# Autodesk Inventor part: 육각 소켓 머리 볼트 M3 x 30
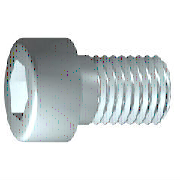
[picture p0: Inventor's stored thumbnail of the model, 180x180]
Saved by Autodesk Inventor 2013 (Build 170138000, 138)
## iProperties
IsCustomPart: 1
Created: 2012-02
Part Number: 육각 소켓 머리 볼트 M3 x 30
Material: 강철, 연강
Description: 6각 소켓 머리 캡 나사
Document SubType Name: Modeling
Standard: ISO 4762
Designer: mdu-01
Standard Revision: Fourth edition 2004-03-01
Standards Organization: ISO
Language: ko-KR
Size Designation: M3 x 30
Categories: <MemberInstance><Categories><Category DisplayName="조임쇠" InternalName="e4da775c-781d-43d5-af7c-5136215cf5a6" Mnemonic="FSTN"><Category DisplayName="볼트" InternalN
Density: 7.75 g/cm^3
Author: mdu-01
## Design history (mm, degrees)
sketch "스케치1"
  geometry: L1 (-0.867, 0)-(30, 0); L2 (30, 0)-(30, 1.5); L3 (30, 1.5)-(12, 1.5); L4 (12, 1.5)-(11.693, 1.5); L5 (11.693, 1.5)-(0, 1.5); L6 (0, 1.5)-(0, 2.75); L7 (0, 2.75)-(-3, 2.75); L8 (-3, 2.75)-(-3, 1.443); L9 (-3, 1.443)-(-1.7, 1.443); L10 (-1.7, 1.443)-(-0.867, 0); L11 (-9.6, 0)-(36.6, 0) reference; L12 (0, -0.55)-(0, 3.3) reference; L13 (12, 1.5)-(0, 1.5)
  constraints: 22 end point, 6 parallel, 2 collinear, 2 perpendicular, 1 horizontal, 1 point on line
  dimensions: "d1" = 18 distance from line of L3.end L2 (= GEL); "d2" = 0.30683 distance of L4.end L3.end (computed from GAL); "d3" = 3 distance between parallel lines of L8 L6 (= KOH); "d4" = 1.3 distance of L8.end L9.end (= INTI); "d5" = 60 deg angle of L10 L1; "d6" = 3 diameter of L3 L1 (= GD); "d7" = 3 diameter of L5 L1 (= BDM); "d8" = 2.88675 diameter of L9 L1 (= 1.1547 x SW); "d9" = 5.5 diameter of L7 L1 (= KOD); "d26" = 30 distance between parallel lines of L12 L2 (= NLG)
revolve "본체" sketch "스케치1" stored, may be unused: angle "d10" = 90 deg
sketch "스케치2"
  geometry: L1 (0, -3.85)-(0, 3.85) reference; L2 (-3.85, 0)-(3.85, 0) reference; L3 (1.443, 0)-(0.722, -1.25); L4 (0.722, -1.25)-(-0.722, -1.25); L5 (-0.722, -1.25)-(-1.443, 0); L6 (-1.443, 0)-(-0.722, 1.25); L7 (-0.722, 1.25)-(0.722, 1.25); L8 (0.722, 1.25)-(1.443, 0); 2 further points
  constraints: 12 end point, 1 coincident, 1 horizontal alignment, 1 point on line, 12 other
extrude "슬롯" join sketch "스케치2" stored distance "d11" = 10; taper "d12" = 0 deg
workplane "Work Plane1"
fillet "Fillet2" dims "d30" = 0.1 (= R)
body "Solid1"
fillet "모깎기1" dims "d17" = 0.3 (= RR)
feature "스레드" dims "d13" = 18 (= GEL), "d14" = 0
chamfer "모따기1" distance "d15" = 0.30673 (= -0.5 x SPD + 0.5 x GD); stored, may be unused: second distance "d16" = 0.30673 (= GUL), angle "d27" = 45 deg
other parameters: "GD" = 3 [user parameter; used in 2 equation terms], "NLG" = 30 [user parameter; used in 1 equation term], "GEL" = 18 [user parameter; used in 2 equation terms], "KOD" = 5.5 [user parameter; used in 1 equation term], "KOH" = 3 [user parameter; used in 1 equation term], "INTI" = 1.3 [user parameter; used in 1 equation term], "GAL" = 0.30673 (= 0.61345 x PTC) [user parameter; used in 1 equation term], "GUL" = 0.30673 (= 0.61345 x PTC) [user parameter; used in 1 equation term], "BDM" = 3 (= NND) [user parameter; used in 1 equation term], "SW" = 2.5 [user parameter; used in 2 equation terms], "RR" = 0.3 [user parameter; used in 1 equation term], "SPD" = 2.38655 (= NND - 1.2269 x PTC) [user parameter; used in 1 equation term], "d19" = 0, "d28" = 0, "d29" = 0, "R" = 0.1 [user parameter; used in 1 equation term], "TOA" = 30 deg [user parameter], "GD1" = 2.38655 (= THREADDIA - 1.2269 x PTC) [user parameter], "THREADDIA" = 3 [user parameter; used in 1 equation term], "FAWI" = 45 deg [user parameter], "PTC" = 0.5 [user parameter; used in 5 equation terms], "NND" = 3 [user parameter; used in 2 equation terms], "E0" = 2.8875 (= 1.155 x SW) [user parameter]
